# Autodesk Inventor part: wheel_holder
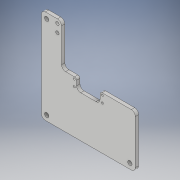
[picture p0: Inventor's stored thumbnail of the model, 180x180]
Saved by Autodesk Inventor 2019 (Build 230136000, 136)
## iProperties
Created: 2018-06
Part Number: wheel_holder
Material: Generic
Document SubType Name: Modeling
Designer: felldings
Density: 1 g/cm^3
Appearance: Default
Author: felldings
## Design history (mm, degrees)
sketch "Sketch8"
  geometry: L1 (0, 0)-(140, 0); L2 (140, 0)-(140, 78); L3 (140, 78)-(87.5, 78); L4 (87.5, 78)-(87.5, 62); L5 (87.5, 62)-(52.5, 62); L6 (52.5, 62)-(52.5, 78); L7 (52.5, 78)-(30, 78); L8 (30, 78)-(30, 140); L9 (30, 140)-(0, 140); L10 (0, 140)-(0, 0); 1 further point
  constraints: 20 end point, 8 perpendicular, 2 point on line, 1 horizontal
  dimensions: "d55" = 70 distance from line of L10 point (70, 70); "d56" = 70 distance from line of L1 point (70, 70); "d57" = 8 distance from line of L5 point (70, 70); "d58" = 16 distance of L5.end L6.end; "d59" = 35 distance of L4.end L5.end; "d60" = 17.5 distance from line of point (70, 70) L6; "d61" = 40 distance from line of point (70, 70) L8; "d62" = 140 distance between parallel lines of L1 L9; "d63" = 140 distance of L1.start L1.end
extrude "base_plate" new body sketch "Sketch8" distance "d64" = 5; taper "d65" = 0 deg
sketch "Sketch9"
  geometry: L1 (52.5, 62)-(52.5, 78) reference; L2 (0, 0)-(140, 0) reference; 4 further points
  dimensions: "d66" = 42 distance of point (91, 65) point (49, 65); "d67" = 42 distance of point (91, 75) point (49, 75); "d68" = 10 distance of point (49, 65) point (49, 75); "d69" = 10 distance of point (91, 65) point (91, 75); "d70" = 3.5 distance from line of L1 point (49, 75); "d71" = 3.5 distance from line of L1 point (49, 65); "d72" = 65 distance from line of L2 point (91, 65); "d73" = 65 distance from line of L2 point (49, 65)
hole "pcb_mount_holes" sketch "Sketch9" at (49, 75), (49, 65), (91, 75), (91, 65) diameter "d74" = 3; stored, may be unused: countersink angle "d78" = 90 deg, drill point angle "d80" = 118 deg; dims "d75" = 6, "d76" = 4, "d77" = 2, "d79" = 8
sketch "Sketch11"
  geometry: L1 (30, 78)-(30, 140) reference; L2 (30, 140)-(0, 140) reference; 4 further points
  dimensions: "d96" = 6 distance from line of L1 point (24, 134); "d97" = 6 distance from line of L1 point (24, 122); "d98" = 6 distance from line of L2 point (24, 134); "d99" = 12 distance of point (24, 134) point (24, 122)
hole "cable_fixation_holes" sketch "Sketch11" at (24, 134), (24, 122) diameter "d100" = 5; stored, may be unused: countersink angle "d104" = 90 deg, drill point angle "d106" = 118 deg; dims "d101" = 6, "d102" = 4, "d103" = 2, "d105" = 8
sketch "Sketch13"
  geometry: L1 (0, 140)-(0, 0) reference; L2 (0, 0)-(-140, 0) reference; L3 (0, 0)-(-140, 0) reference; L4 (-140, 0)-(-140, 78) reference; L5 (-30, 140)-(0, 140) reference; 5 further points
  dimensions: "d109" = 8 distance from line of L1 point (-8, 8); "d110" = 8 distance from line of L2 point (-8, 8); "d111" = 8 distance from line of L3 point (-132, 8); "d112" = 8 distance from line of L4 point (-132, 8); "d113" = 8 distance from line of L5 point (-8, 132); "d114" = 8 distance from line of L1 point (-8, 132)
hole "grouping_holes" sketch "Sketch13" at (-8, 8), (-8, 132), (-132, 8) diameter "d115" = 6.5; stored, may be unused: countersink angle "d119" = 90 deg, drill point angle "d121" = 118 deg; dims "d116" = 6, "d117" = 4, "d118" = 2, "d120" = 8
fillet "Fillet8" dims "d137" = 6
fillet "Fillet9" dims "d138" = 3
body "Solid3"
